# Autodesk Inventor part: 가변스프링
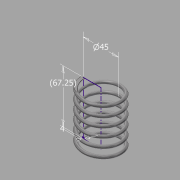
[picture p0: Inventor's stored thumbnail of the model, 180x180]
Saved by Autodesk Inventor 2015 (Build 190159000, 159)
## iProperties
Created: 2016-02
Part Number: 가변스프링
Material: 스테인레스 스틸
Document SubType Name: Modeling
Designer: Administrator
Density: 8 g/cm^3
Appearance: 반연마
Mass: 84.2127 g
Surface Area: 106.464 cm^2
Volume: 10.5266 cm^3
Author: Administrator
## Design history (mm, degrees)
sketch "스케치1"
  geometry: L1 (0, 0)-(22.5, 0); L2 (22.5, 0)-(22.5, 67.25); L3 (22.5, 67.25)-(0, 67.25); L4 (0, 67.25)-(0, 0); C1 r 2 at (22.5, 0)
  constraints: 8 end point, 2 parallel, 1 centre point, 1 coincident, 1 horizontal, 1 perpendicular
  dimensions: "d0" = 67.25 distance of L1.end L2.end (derived); "d1" = 45 diameter of L2 L4; "d2" = 4 diameter of C1
feature "코일1" sketch "스케치1" pitch "d3" = 10; turns "d5" = 6; dims "d4" = 67.25 (= d0), "d6" = 0, angle "d7" = 90 deg, angle "d8" = 90 deg, "d9" = 0, "d10" = 0
sketch "스케치2"
  geometry: L1 (-20.5, 0)-(-24.5, 0) reference; 1 further point
  constraints: 1 horizontal alignment
extrude "돌출1" cut sketch "스케치2" stored distance "d11" = 10; taper "d12" = 0 deg
node "작업 평면1"
sketch "스케치3"
  geometry: L1 (-2, 0)-(2, 0) reference; 1 further point
  constraints: 1 horizontal alignment
extrude "돌출2" cut sketch "스케치3" stored distance "d13" = 10; taper "d14" = 0 deg
node "솔리드1"
node "절단 모서리 투영1"
node "절단 모서리 투영2"
